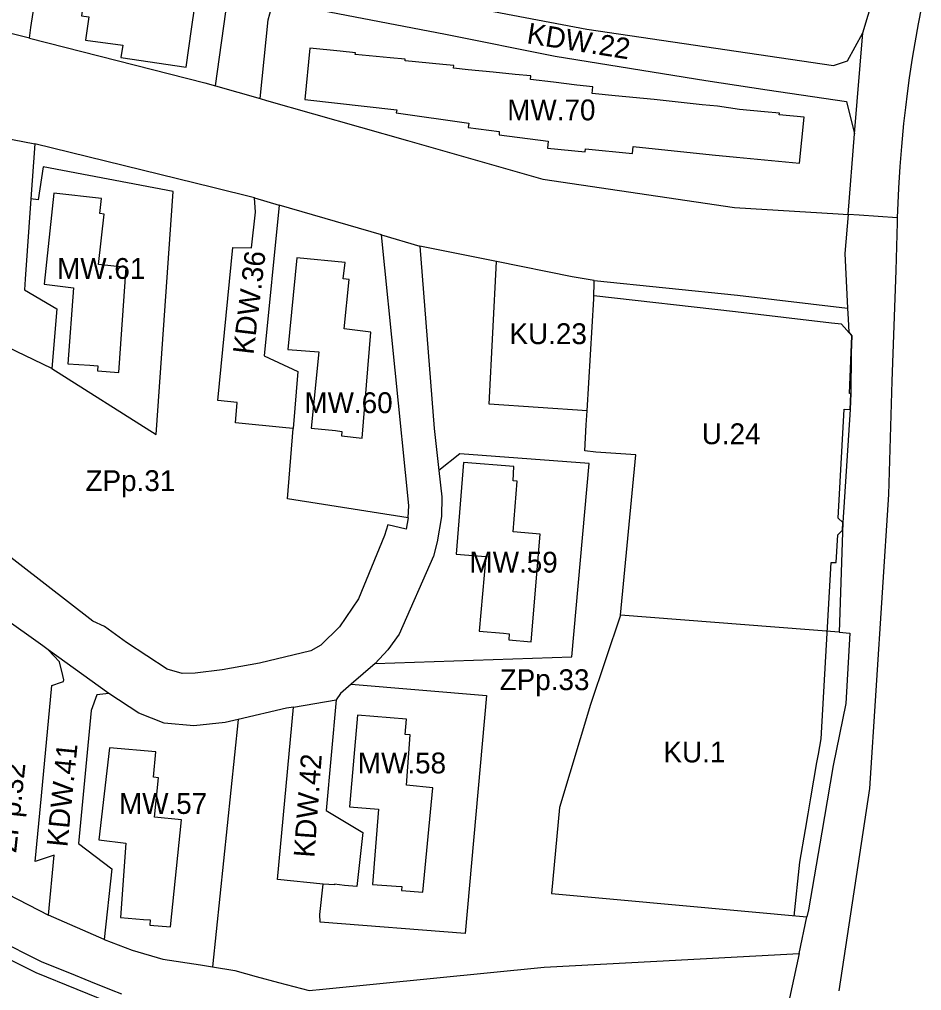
# Model space of a CAD drawing. Extents: x 7424434 to 7425898, y 5541432 to 5542659.
# Drawn here: x 7425520.4 to 7425737, y 5541617.4 to 5541850.5 of the extents above; entities that cross this region are included whole.
import ezdxf

# ---------------------------------------------------------------- set-up
doc = ezdxf.new("R2010")
doc.units = 0
for name, color, linetype in [('linie rozgraniczające', 7, 'Continuous'), ('nieprzekraczalne linie zabudowy', 7, 'Continuous'), ('obowiazujace linie zabudowy', 7, 'Continuous'), ('przeznaczenia terenów', 7, 'Continuous')]:
    doc.layers.add(name, color=color, linetype=linetype)

msp = doc.modelspace()

# ---------------------------------------------------------------- linework, layer by layer
at = {"layer": 'linie rozgraniczające'}
for p, q in [((7425567.48, 5541834.53), (7425573.8, 5541880.23)), ((7425722.86, 5541847.26), (7425730.25, 5541871.57)), ((7425583.05, 5541862.1), (7425656.63, 5541848.13)), ((7425523.18, 5541848.5), (7425524.73, 5541859.15)), ((7425591.03, 5541853.01), (7425622.72, 5541846.9)), ((7425736.98, 5541853.51), (7425736.17, 5541849.39)), ((7425578.19, 5541831.48), (7425580.13, 5541850.37)), ((7425736.17, 5541849.39), (7425735.34, 5541844.8)), ((7425522.8, 5541845.92), (7425516.46, 5541847.52)), ((7425522.8, 5541845.92), (7425523.18, 5541848.5)), ((7425622.72, 5541846.9), (7425649.05, 5541841.65)), ((7425656.63, 5541848.13), (7425715.8, 5541839.39)), ((7425719.17, 5541840.5), (7425722.86, 5541847.26)), ((7425720.9, 5541822.98), (7425722.86, 5541847.26)), ((7425522.8, 5541845.92), (7425564.89, 5541835.27)), ((7425735.34, 5541844.8), (7425734.74, 5541841.19)), ((7425649.05, 5541841.65), (7425685.18, 5541835.79)), ((7425715.8, 5541839.39), (7425719.17, 5541840.5)), ((7425734.74, 5541841.19), (7425734.02, 5541836.43)), ((7425564.89, 5541835.27), (7425567.48, 5541834.53)), ((7425685.18, 5541835.79), (7425699.9, 5541833.6)), ((7425734.02, 5541836.43), (7425733.51, 5541832.71)), ((7425567.48, 5541834.53), (7425578.19, 5541831.48)), ((7425699.9, 5541833.6), (7425718.97, 5541830.76)), ((7425733.51, 5541832.71), (7425733.08, 5541829.3)), ((7425578.19, 5541831.48), (7425579.74, 5541831.04)), ((7425579.74, 5541831.04), (7425613.59, 5541821.4)), ((7425718.97, 5541830.76), (7425720.9, 5541822.98)), ((7425733.08, 5541829.3), (7425732.66, 5541825.52)), ((7425732.66, 5541825.52), (7425732.12, 5541820)), ((7425613.59, 5541821.4), (7425646.08, 5541812.15)), ((7425719.33, 5541803.62), (7425720.9, 5541822.98)), ((7425524.07, 5541820.61), (7425523.15, 5541807.43)), ((7425566.86, 5541810.1), (7425524.07, 5541820.61)), ((7425732.12, 5541820), (7425731.73, 5541815.14)), ((7425526.12, 5541815.09), (7425524.9, 5541807.17)), ((7425557.29, 5541809.13), (7425526.12, 5541815.09)), ((7425731.73, 5541815.14), (7425731.41, 5541809.96)), ((7425646.08, 5541812.15), (7425692.05, 5541805.32)), ((7425576.86, 5541807.64), (7425566.86, 5541810.1)), ((7425731.41, 5541809.96), (7425731.13, 5541802.88)), ((7425523.15, 5541807.43), (7425521.81, 5541788.15)), ((7425524.9, 5541807.17), (7425523.15, 5541807.43)), ((7425553.24, 5541750.85), (7425557.29, 5541809.13)), ((7425576.86, 5541807.64), (7425582.76, 5541805.92)), ((7425577.09, 5541804.19), (7425576.86, 5541807.64)), ((7425582.76, 5541805.92), (7425579.19, 5541769.72)), ((7425607.29, 5541798.75), (7425582.76, 5541805.92)), ((7425692.05, 5541805.32), (7425716.93, 5541803.77)), ((7425576.14, 5541795.61), (7425577.09, 5541804.19)), ((7425716.93, 5541803.77), (7425719.33, 5541803.62)), ((7425719.33, 5541803.62), (7425718.58, 5541794.32)), ((7425721.97, 5541803.45), (7425719.33, 5541803.62)), ((7425731.13, 5541802.88), (7425721.97, 5541803.45)), ((7425731.13, 5541802.88), (7425731.08, 5541801.73)), ((7425731.08, 5541801.73), (7425730.78, 5541790.21)), ((7425613.89, 5541733.83), (7425607.29, 5541798.75)), ((7425607.29, 5541798.75), (7425616.49, 5541796.06)), ((7425568.06, 5541759), (7425571.6, 5541795.71)), ((7425571.6, 5541795.71), (7425576.14, 5541795.61)), ((7425634.93, 5541792.37), (7425616.49, 5541796.06)), ((7425616.49, 5541796.06), (7425619.98, 5541752.32)), ((7425718.58, 5541794.32), (7425719.22, 5541781.16)), ((7425633.16, 5541758.17), (7425634.93, 5541792.37)), ((7425653.13, 5541788.73), (7425634.93, 5541792.37)), ((7425658.4, 5541787.85), (7425653.13, 5541788.73)), ((7425730.78, 5541790.21), (7425729.83, 5541763.67)), ((7425521.81, 5541788.15), (7425521.63, 5541785.6)), ((7425658.26, 5541783.43), (7425658.4, 5541787.85)), ((7425658.4, 5541787.85), (7425692.8, 5541784.26)), ((7425521.63, 5541785.6), (7425529.38, 5541781.01)), ((7425692.8, 5541784.26), (7425719.22, 5541781.16)), ((7425656.67, 5541756.51), (7425658.26, 5541783.43)), ((7425529.38, 5541781.01), (7425528.15, 5541766.73)), ((7425719.22, 5541781.16), (7425719.34, 5541778.57)), ((7425719.34, 5541778.57), (7425719.48, 5541775.39)), ((7425719.48, 5541775.39), (7425720.24, 5541774.55)), ((7425720.24, 5541774.55), (7425720.06, 5541770.34)), ((7425528.15, 5541766.73), (7425515.3, 5541772.85)), ((7425579.19, 5541769.72), (7425587.24, 5541765.97)), ((7425720.06, 5541770.34), (7425720.02, 5541760.67)), ((7425528.15, 5541766.73), (7425553.24, 5541750.85)), ((7425587.24, 5541765.97), (7425586.1, 5541752.32)), ((7425729.83, 5541763.67), (7425729.01, 5541736.5)), ((7425720.02, 5541760.67), (7425719.86, 5541756.87)), ((7425572.69, 5541758.53), (7425568.06, 5541759)), ((7425572.27, 5541753.65), (7425572.69, 5541758.53)), ((7425656.67, 5541756.51), (7425633.16, 5541758.17)), ((7425656.47, 5541753.18), (7425656.67, 5541756.51)), ((7425719.86, 5541756.87), (7425718.06, 5541729.72)), ((7425584.37, 5541752.48), (7425572.27, 5541753.65)), ((7425586.1, 5541752.32), (7425584.37, 5541752.48)), ((7425584.75, 5541735.42), (7425586.1, 5541752.32)), ((7425619.98, 5541752.32), (7425621.11, 5541742.21)), ((7425656.1, 5541746.94), (7425656.47, 5541753.18)), ((7425658.81, 5541746.61), (7425656.1, 5541746.94)), ((7425668.41, 5541745.98), (7425658.81, 5541746.61)), ((7425626.12, 5541746.2), (7425621.11, 5541742.21)), ((7425657.2, 5541743.89), (7425626.12, 5541746.2)), ((7425664.73, 5541707.52), (7425668.41, 5541745.98)), ((7425621.11, 5541742.21), (7425621.81, 5541735.88)), ((7425653.03, 5541697.54), (7425657.2, 5541743.89)), ((7425613.71, 5541730.86), (7425584.75, 5541735.42)), ((7425621.81, 5541735.88), (7425621.69, 5541731.19)), ((7425729.01, 5541736.5), (7425724.48, 5541665.9)), ((7425613.71, 5541730.86), (7425613.89, 5541733.83)), ((7425613.71, 5541730.86), (7425613.21, 5541728.13)), ((7425621.69, 5541731.19), (7425620.71, 5541725.12)), ((7425608.85, 5541729.2), (7425608.06, 5541726.63)), ((7425613.21, 5541728.13), (7425608.85, 5541729.2)), ((7425718.06, 5541729.72), (7425717.2, 5541703.4)), ((7425538, 5541706.09), (7425512.02, 5541726.19)), ((7425608.06, 5541726.63), (7425601.83, 5541711.45)), ((7425620.71, 5541725.12), (7425619.78, 5541721.66)), ((7425619.78, 5541721.66), (7425611.56, 5541702.99)), ((7425601.83, 5541711.45), (7425597.23, 5541704.74)), ((7425526.02, 5541700.16), (7425516.3, 5541707.13)), ((7425664.73, 5541707.52), (7425657.52, 5541686.09)), ((7425717.2, 5541703.4), (7425664.73, 5541707.52)), ((7425540.87, 5541704.79), (7425538, 5541706.09)), ((7425546.15, 5541700.97), (7425540.87, 5541704.79)), ((7425597.23, 5541704.74), (7425592.75, 5541700.33)), ((7425611.56, 5541702.99), (7425608.86, 5541699.23)), ((7425717.2, 5541703.4), (7425719.76, 5541703.2)), ((7425719.76, 5541703.2), (7425718.76, 5541686.31)), ((7425527.32, 5541699.23), (7425526.02, 5541700.16)), ((7425555.88, 5541694.59), (7425546.15, 5541700.97)), ((7425592.75, 5541700.33), (7425590.4, 5541698.92)), ((7425541.89, 5541688.71), (7425527.32, 5541699.23)), ((7425530.02, 5541696.32), (7425527.32, 5541699.23)), ((7425590.4, 5541698.92), (7425578.06, 5541695.96)), ((7425608.86, 5541699.23), (7425605.79, 5541695.88)), ((7425605.79, 5541695.88), (7425653.03, 5541697.54)), ((7425530.82, 5541693.07), (7425530.02, 5541696.32)), ((7425578.06, 5541695.96), (7425569.11, 5541694.39)), ((7425605.79, 5541695.88), (7425600.08, 5541690.99)), ((7425531.09, 5541691.99), (7425530.82, 5541693.07)), ((7425559.5, 5541693.54), (7425555.88, 5541694.59)), ((7425562.62, 5541693.58), (7425559.5, 5541693.54)), ((7425569.11, 5541694.39), (7425562.62, 5541693.58)), ((7425525.69, 5541664.2), (7425528.15, 5541690.64)), ((7425528.15, 5541690.64), (7425530.54, 5541691.45)), ((7425530.54, 5541691.45), (7425530.97, 5541691.6)), ((7425530.97, 5541691.6), (7425531.09, 5541691.99)), ((7425600.08, 5541690.99), (7425597.45, 5541688.75)), ((7425600.08, 5541690.99), (7425632.55, 5541688.22)), ((7425538.99, 5541688.42), (7425537.59, 5541684.62)), ((7425541.89, 5541688.71), (7425538.99, 5541688.42)), ((7425549.1, 5541683.99), (7425541.89, 5541688.71)), ((7425597.45, 5541688.75), (7425596.43, 5541687.2)), ((7425632.55, 5541688.22), (7425627.41, 5541631.09)), ((7425586.2, 5541685.45), (7425596.43, 5541687.2)), ((7425596.43, 5541687.2), (7425594.06, 5541660.66)), ((7425657.52, 5541686.09), (7425650.08, 5541661.34)), ((7425718.76, 5541686.31), (7425715.78, 5541671.4)), ((7425537.59, 5541684.62), (7425534.59, 5541652.76)), ((7425555.13, 5541681.6), (7425549.1, 5541683.99)), ((7425584.55, 5541685.16), (7425572.89, 5541682.49)), ((7425582.39, 5541644.08), (7425586.2, 5541685.45)), ((7425586.2, 5541685.45), (7425584.55, 5541685.16)), ((7425562.31, 5541680.93), (7425555.13, 5541681.6)), ((7425569.81, 5541681.78), (7425562.31, 5541680.93)), ((7425572.89, 5541682.49), (7425566.79, 5541623.15)), ((7425572.89, 5541682.49), (7425569.81, 5541681.78)), ((7425715.78, 5541671.4), (7425714.32, 5541662.97)), ((7425724.48, 5541665.9), (7425717.08, 5541617.4)), ((7425524.21, 5541648.37), (7425525.69, 5541664.2)), ((7425714.32, 5541662.97), (7425713.67, 5541659.17)), ((7425594.06, 5541660.66), (7425602.85, 5541655.39)), ((7425650.08, 5541661.34), (7425648.12, 5541640.75)), ((7425713.67, 5541659.17), (7425713.02, 5541655.43)), ((7425602.85, 5541655.39), (7425601.38, 5541642.41)), ((7425713.02, 5541655.43), (7425709.81, 5541636.8)), ((7425534.59, 5541652.76), (7425542.6, 5541646.63)), ((7425528.75, 5541649.94), (7425524.21, 5541648.37)), ((7425527.38, 5541635.55), (7425528.75, 5541649.94)), ((7425542.6, 5541646.63), (7425540.77, 5541629.7)), ((7425510.85, 5541644.02), (7425527.38, 5541635.55)), ((7425593.3, 5541642.96), (7425582.39, 5541644.08)), ((7425592.51, 5541635.72), (7425593.3, 5541642.96)), ((7425596.04, 5541642.78), (7425593.3, 5541642.96)), ((7425596.06, 5541642.93), (7425596.04, 5541642.78)), ((7425598.47, 5541642.61), (7425596.06, 5541642.93)), ((7425601.38, 5541642.41), (7425598.47, 5541642.61)), ((7425648.12, 5541640.75), (7425709.45, 5541635.14)), ((7425540.76, 5541629.65), (7425527.38, 5541635.55)), ((7425592.59, 5541633.88), (7425592.51, 5541635.72)), ((7425707.56, 5541626.36), (7425709.45, 5541635.14)), ((7425709.81, 5541636.8), (7425709.45, 5541635.14)), ((7425627.41, 5541631.09), (7425592.59, 5541633.88)), ((7425517.85, 5541628.32), (7425522.55, 5541625.95)), ((7425540.77, 5541629.7), (7425540.76, 5541629.65)), ((7425540.76, 5541629.65), (7425547.51, 5541627.1)), ((7425522.55, 5541625.95), (7425525.63, 5541624.4)), ((7425547.51, 5541627.1), (7425554.84, 5541624.99)), ((7425673.46, 5541624.52), (7425707.56, 5541626.36)), ((7425707.56, 5541626.36), (7425706.91, 5541623.36)), ((7425525.63, 5541624.4), (7425527.37, 5541623.7)), ((7425527.37, 5541623.7), (7425532.4, 5541621.66)), ((7425554.84, 5541624.99), (7425563.84, 5541623.65)), ((7425563.84, 5541623.65), (7425566.79, 5541623.15)), ((7425566.79, 5541623.15), (7425572.1, 5541622.24)), ((7425593.25, 5541617.8), (7425646.4, 5541623.06)), ((7425646.4, 5541623.06), (7425673.46, 5541624.52)), ((7425706.91, 5541623.36), (7425705.24, 5541615.6)), ((7425532.4, 5541621.66), (7425537.44, 5541619.63)), ((7425572.1, 5541622.24), (7425577.25, 5541620.81)), ((7425577.25, 5541620.81), (7425582.62, 5541619.4)), ((7425537.44, 5541619.63), (7425542.47, 5541617.59)), ((7425582.62, 5541619.4), (7425589.93, 5541617.47)), ((7425542.47, 5541617.59), (7425544.88, 5541616.62)), ((7425589.93, 5541617.47), (7425593.25, 5541617.8))]:
    msp.add_line(p, q, dxfattribs=at)
for points in [[(7425580.13, 5541850.37), (7425581.34, 5541854.71), (7425581.38, 5541854.84)], [(7425469.86, 5541830.93), (7425516.28, 5541822.09), (7425524.07, 5541820.61)]]:
    msp.add_lwpolyline(points, dxfattribs=at)
at = {"layer": 'nieprzekraczalne linie zabudowy'}
msp.add_lwpolyline([(7425706.38, 5541635.28), (7425707.72, 5541648.24), (7425709.08, 5541656.11), (7425709.73, 5541659.85), (7425710.38, 5541663.65), (7425711.85, 5541672.13), (7425712.25, 5541674.13), (7425712.84, 5541677.86), (7425715.24, 5541720.18), (7425716.49, 5541720.12), (7425716.86, 5541726.82), (7425718, 5541727.88), (7425718.06, 5541729.72), (7425716.95, 5541730.75), (7425718.41, 5541756.93), (7425719.86, 5541756.87), (7425720.02, 5541760.67), (7425719.65, 5541760.68), (7425720.24, 5541774.55), (7425717.74, 5541777.31), (7425715.38, 5541777.58), (7425692.34, 5541780.29), (7425658.3, 5541784.12)], dxfattribs=at)
msp.add_lwpolyline([(7425516.21, 5541550.81), (7425539.76, 5541559.82), (7425542.87, 5541562.42), (7425566.11, 5541581.87), (7425568.69, 5541610.4), (7425544.11, 5541613.7), (7425524.39, 5541621.67), (7425514.3, 5541626.75), (7425462.65, 5541652.8), (7425423.35, 5541666), (7425404.27, 5541669.87), (7425401.75, 5541646.75), (7425399.07, 5541622.15), (7425398.91, 5541620.78), (7425392.88, 5541565.32), (7425432.43, 5541559.06), (7425432.38, 5541558.61), (7425444.12, 5541557.2), (7425463.89, 5541554.08), (7425469.74, 5541553.7)], close=True, dxfattribs=at)
at = {"layer": 'obowiazujace linie zabudowy'}
for points in [[(7425563.98, 5541863.55), (7425565.29, 5541872.52), (7425566.18, 5541878.66), (7425562.64, 5541879.17), (7425562.85, 5541880.33), (7425556.98, 5541881.21), (7425550.77, 5541882.1), (7425545.32, 5541882.88), (7425545.16, 5541881.69), (7425533.58, 5541883.37), (7425532.7, 5541877.25), (7425531.89, 5541871.64), (7425533.67, 5541871.36), (7425538.1, 5541870.67), (7425535.31, 5541851.35), (7425537.08, 5541851.11), (7425536.29, 5541845.44), (7425545.21, 5541844.25), (7425544.78, 5541841.28), (7425560.4, 5541839.01), (7425561.72, 5541848.09), (7425563.43, 5541859.79), (7425563.98, 5541863.55)], [(7425588.9, 5541831.24), (7425611, 5541828.73), (7425610.87, 5541828.07), (7425628.33, 5541825.54), (7425628.11, 5541824.51), (7425635.6, 5541823.55), (7425635.55, 5541822.78), (7425647.37, 5541821.23), (7425647.21, 5541819.58), (7425656.24, 5541818.7), (7425656.31, 5541819.41), (7425667.6, 5541818.3), (7425667.77, 5541819.97), (7425686.72, 5541817.99), (7425692.54, 5541817.41), (7425707.68, 5541815.94), (7425708.76, 5541826.97), (7425702.79, 5541827.55), (7425702.83, 5541827.93), (7425699.23, 5541828.28), (7425693.25, 5541828.86), (7425687.96, 5541829.65), (7425684.32, 5541830), (7425672.75, 5541831.21), (7425663.39, 5541832.11), (7425657.86, 5541832.72), (7425658.02, 5541834.31), (7425654.19, 5541834.69), (7425648.64, 5541835.39), (7425643.11, 5541836.03), (7425643.19, 5541836.88), (7425639.45, 5541837.25), (7425634.12, 5541837.78), (7425628.17, 5541838.37), (7425624.62, 5541838.72), (7425624.66, 5541839.37), (7425622.01, 5541839.63), (7425612.98, 5541840.52), (7425613.01, 5541840.88), (7425609.44, 5541841.23), (7425601.03, 5541842.05), (7425601.07, 5541842.44), (7425597.37, 5541842.81), (7425590.12, 5541843.54)], [(7425533.36, 5541786.06), (7425532.01, 5541767.82), (7425537.29, 5541767.46), (7425539.23, 5541767.33), (7425539.14, 5541766.1), (7425544.25, 5541765.75), (7425546, 5541790.93), (7425539.42, 5541791.67), (7425540.79, 5541803.73), (7425539.7, 5541803.92), (7425540.13, 5541807.46), (7425528.65, 5541808.76), (7425526.32, 5541786.9)], [(7425586.99, 5541793.23), (7425584.82, 5541771.29), (7425592.28, 5541770.66), (7425590.45, 5541752.38), (7425596.27, 5541751.79), (7425597.84, 5541751.61), (7425597.74, 5541750.53), (7425602.7, 5541749.96), (7425604.75, 5541775.41), (7425598.33, 5541776.22), (7425599.54, 5541788.05), (7425598.16, 5541788.22), (7425598.61, 5541792.16)], [(7425626.98, 5541744.11), (7425625.24, 5541722.14), (7425632.37, 5541721.57), (7425630.81, 5541703.68), (7425636.61, 5541703.18), (7425637.98, 5541703.06), (7425637.86, 5541701.58), (7425643.27, 5541701.11), (7425645.38, 5541726.98), (7425638.91, 5541727.51), (7425639.9, 5541739.63), (7425638.93, 5541739.71), (7425639.1, 5541743.21)], [(7425601.53, 5541683.52), (7425599.61, 5541661.55), (7425606.58, 5541660.94), (7425605.14, 5541642.91), (7425610.88, 5541642.45), (7425612.21, 5541642.44), (7425612.13, 5541641.43), (7425617.28, 5541641.02), (7425619.62, 5541666.09), (7425613.33, 5541666.68), (7425614.22, 5541678.78), (7425613.02, 5541678.87), (7425613.29, 5541682.53)], [(7425542.01, 5541675.66), (7425539.46, 5541653.58), (7425545.97, 5541652.83), (7425544.68, 5541634.93), (7425550.23, 5541634.5), (7425551.78, 5541634.38), (7425551.68, 5541633.09), (7425556.71, 5541632.7), (7425559.34, 5541658.38), (7425552.83, 5541659.05), (7425553.8, 5541668.47), (7425552.56, 5541668.6), (7425553.18, 5541674.69)]]:
    msp.add_lwpolyline(points, close=True, dxfattribs=at)

# ---------------------------------------------------------------- texts
at = {"layer": 'przeznaczenia terenów'}
for s, rotation, p in [('KDW.22', 351, (7425642, 5541844.75)), ('KDW.36', 83.164, (7425576.58, 5541769.89)), ('KDW.41', 84.2726, (7425531.9, 5541651.75)), ('ZPp.32', 84, (7425519.63, 5541650.41)), ('KDW.42', 85.8318, (7425591.21, 5541649.22))]:
    msp.add_text(s, height=5, rotation=rotation, dxfattribs=at).set_placement(p)
for s, p in [('MW.70', (7425637.51, 5541826.24)), ('MW.61', (7425529.46, 5541788.2)), ('KU.23', (7425638.05, 5541772.55)), ('MW.60', (7425588.83, 5541755.99)), ('U.24', (7425684.21, 5541748.53)), ('ZPp.31', (7425536.27, 5541737.28)), ('MW.59', (7425628.46, 5541717.72)), ('ZPp.33', (7425635.69, 5541689.52)), ('KU.1', (7425675.01, 5541672.18)), ('MW.58', (7425601.65, 5541669.54)), ('MW.57', (7425544.31, 5541659.82))]:
    msp.add_text(s, height=5, dxfattribs=at).set_placement(p)

doc.saveas('drawing.dxf')
